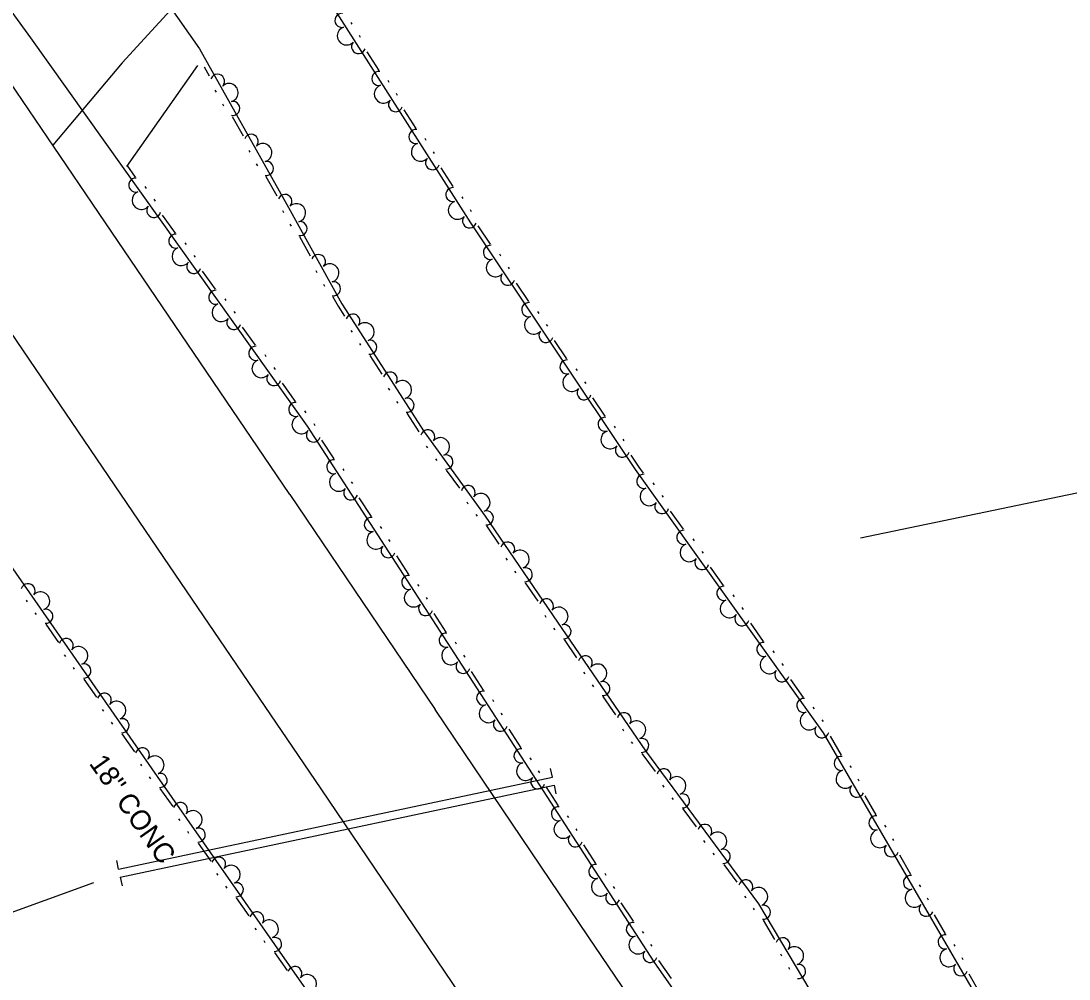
# Model space of a CAD drawing. Extents: x 2030130 to 2036320, y 723205 to 762423.
# Drawn here: x 2032932.6 to 2033126.1, y 761768 to 761944.8 of the extents above; entities that cross this region are included whole.
import ezdxf

# ---------------------------------------------------------------- set-up
doc = ezdxf.new("R2010")
doc.units = 0
for name, color, linetype in [('Draft_Station Labels Major', 7, 'Continuous'), ('Draft_Station Tics Major', 7, 'Continuous'), ('Draft_Station Tics Minor', 7, 'Continuous'), ('Old_Level_26', 7, 'Continuous'), ('Prop Alignment Horizontal', 7, 'Continuous')]:
    doc.layers.add(name, color=color, linetype=linetype)

msp = doc.modelspace()

# ---------------------------------------------------------------- linework, layer by layer
at = {"layer": 'Draft_Station Labels Major'}
for p, q in [((2032951.33, 761937.1), (2032938.5, 761921.91)), ((2032982.25, 761857.44), (2033009.06, 761817.74)), ((2032959.96, 761844.28), (2032987.95, 761803.12))]:
    msp.add_line(p, q, dxfattribs=at)
for points in [[(2032982.25, 761857.44), (2032953.98, 761899.13), (2032895.43, 761985.31), (2032867.48, 762026.64), (2032839.86, 762067.31), (2032810.94, 762109.31), (2032783.52, 762149.89), (2032755.69, 762190.54), (2032727.21, 762232.52), (2032699.29, 762273.24), (2032670.84, 762315.05), (2032643.99, 762354.39), (2032615.89, 762395.7), (2032597.19, 762422.99)], [(2032578.53, 762404.38), (2032622.03, 762340.46), (2032649.81, 762299.71), (2032677.92, 762258.76), (2032706.15, 762217.66), (2032734.05, 762176.43), (2032762.1, 762135.36), (2032790.25, 762094.19), (2032818.14, 762052.99), (2032846.2, 762011.84), (2032874.09, 761970.67), (2032902.04, 761929.59), (2032931.85, 761885.67), (2032959.96, 761844.28)], [(2032951.33, 761937.1), (2032972.48, 761960.26), (2032985.71, 761977.44)], [(2033317.86, 761363.04), (2033290.43, 761403.19), (2033260.47, 761446.88), (2033232.75, 761487.83), (2033204.6, 761528.87), (2033176.73, 761570.42), (2033148.96, 761611.47), (2033120.54, 761652.92), (2033093.45, 761693.44), (2033064.45, 761735.88), (2033037.38, 761775.77), (2033009.06, 761817.74)], [(2032987.95, 761803.12), (2033043.65, 761720.79), (2033056.64, 761702.34), (2033057.8, 761696.58), (2033076.72, 761668.89), (2033082.75, 761662.9), (2033099.45, 761638.44), (2033127.47, 761597.33), (2033155.33, 761556.18), (2033183.52, 761515.12), (2033211.27, 761473.78), (2033239.33, 761432.83), (2033268.78, 761389.51), (2033297.27, 761347.85)]]:
    msp.add_lwpolyline(points, dxfattribs=at)
at = {"layer": 'Draft_Station Tics Major'}
msp.add_line((2032952.18, 761917.95), (2032965.29, 761936.63), dxfattribs=at)
for points in [[(2033121.18, 761743.95), (2033080.74, 761813.47), (2033046.05, 761862.02), (2033015.65, 761907.58), (2032980.17, 761963.3), (2032941.81, 762027.2), (2032908.21, 762064.45), (2032877.87, 762105.34)], [(2033107.4, 761688.4), (2033049.51, 761771.21), (2032985.52, 761870.07), (2032934.46, 761941.71), (2032872.35, 762027.01), (2032832.35, 762090.98)], [(2032857.5, 762090.26), (2032871.14, 762073.87), (2032878.45, 762062.18), (2032888.1, 762049.28), (2032898.38, 762032.64), (2032910.79, 762015.75), (2032922.64, 761999.26), (2032936.88, 761980.71), (2032951.77, 761959.4), (2032965.55, 761939.68), (2032981.68, 761910.94), (2032991.86, 761892.63), (2033007.03, 761869.02), (2033018.32, 761853.44), (2033031.66, 761833.88), (2033047.89, 761810.12), (2033068.77, 761781.86), (2033086.33, 761752.31)], [(2032987.59, 761762.73), (2032957.8, 761805.4), (2032921.13, 761858.06), (2032890.88, 761904.34), (2032862.59, 761942.95), (2032834.05, 761983.65), (2032801.35, 762033.01), (2032781.96, 762059.34)], [(2032993.78, 761944.22), (2032993.56, 761944.57)], [(2032995.32, 761941.81), (2032995.1, 761942.15)], [(2032998.72, 761935.7), (2032996.52, 761939.16)], [(2032966.46, 761936.39), (2032967.39, 761934.73)], [(2033000.61, 761933.5), (2033000.39, 761933.85)], [(2032968.44, 761932.03), (2032968.64, 761931.67)], [(2033002.15, 761931.08), (2033001.93, 761931.43)], [(2032969.84, 761929.53), (2032970.04, 761929.17)], [(2032971.6, 761927.22), (2032973.61, 761923.65)], [(2033005.55, 761924.98), (2033003.35, 761928.44)], [(2033007.44, 761922.78), (2033007.21, 761923.12)], [(2032974.66, 761920.94), (2032974.86, 761920.59)], [(2033008.98, 761920.36), (2033008.76, 761920.7)], [(2032953.77, 761916.03), (2032952.21, 761918.22)], [(2032976.06, 761918.44), (2032976.26, 761918.08)], [(2033012.38, 761914.25), (2033010.17, 761917.71)], [(2032977.83, 761916.14), (2032979.83, 761912.56)], [(2032955.77, 761913.93), (2032955.53, 761914.26)], [(2032957.44, 761911.59), (2032957.2, 761911.92)], [(2033014.26, 761912.05), (2033014.04, 761912.4)], [(2032980.88, 761909.86), (2032981.08, 761909.5)], [(2033015.81, 761909.63), (2033015.58, 761909.98)], [(2032961.15, 761905.67), (2032958.77, 761909.01)], [(2032982.27, 761907.35), (2032982.47, 761906.99)], [(2033019.29, 761903.61), (2033017.01, 761907.02)], [(2032963.15, 761903.58), (2032962.91, 761903.91)], [(2032984.02, 761905.04), (2032986.01, 761901.46)], [(2033021.22, 761901.45), (2033021, 761901.79)], [(2032964.82, 761901.24), (2032964.58, 761901.57)], [(2032968.53, 761895.32), (2032966.15, 761898.66)], [(2032987.05, 761898.75), (2032987.25, 761898.39)], [(2033022.82, 761899.06), (2033022.59, 761899.4)], [(2032988.44, 761896.24), (2032988.64, 761895.88)], [(2033026.35, 761893.03), (2033024.07, 761896.44)], [(2032990.2, 761893.93), (2032991.15, 761892.2), (2032992.33, 761890.37)], [(2032970.53, 761893.22), (2032970.29, 761893.56)], [(2032972.2, 761890.88), (2032971.96, 761891.22)], [(2033028.28, 761890.87), (2033028.05, 761891.21)], [(2032975.91, 761884.97), (2032973.53, 761888.31)], [(2033029.87, 761888.48), (2033029.64, 761888.83)], [(2032993.54, 761887.73), (2032993.76, 761887.39)], [(2032995.09, 761885.32), (2032995.31, 761884.97)], [(2033033.4, 761882.46), (2033031.13, 761885.87)], [(2032977.91, 761882.87), (2032977.67, 761883.2)], [(2032996.99, 761883.12), (2032999.21, 761879.67)], [(2032979.58, 761880.53), (2032979.34, 761880.87)], [(2033035.34, 761880.3), (2033035.11, 761880.64)], [(2032983.29, 761874.62), (2032980.91, 761877.96)], [(2033000.42, 761877.04), (2033000.64, 761876.69)], [(2033036.93, 761877.91), (2033036.7, 761878.25)], [(2033001.97, 761874.62), (2033002.19, 761874.28)], [(2033040.46, 761871.88), (2033038.18, 761875.29)], [(2032985.29, 761872.52), (2032985.05, 761872.85)], [(2033003.87, 761872.43), (2033006.08, 761868.98)], [(2032986.96, 761870.11), (2032986.74, 761870.46)], [(2033042.39, 761869.72), (2033042.17, 761870.06)], [(2032990.41, 761864.04), (2032988.18, 761867.48)], [(2033043.98, 761867.33), (2033043.76, 761867.67)], [(2033007.44, 761866.36), (2033007.68, 761866.03)], [(2033009.12, 761864.04), (2033009.37, 761863.7)], [(2033047.54, 761861.35), (2033046.72, 761862.49), (2033045.24, 761864.72)], [(2032992.31, 761861.85), (2032992.09, 761862.2)], [(2033011.14, 761861.95), (2033013.55, 761858.63)], [(2032993.87, 761859.44), (2032993.64, 761859.79)], [(2033049.54, 761859.25), (2033049.3, 761859.59)], [(2033051.21, 761856.92), (2033050.97, 761857.25)], [(2032997.31, 761853.37), (2032995.08, 761856.81)], [(2033014.9, 761856.07), (2033015.14, 761855.74)], [(2033016.58, 761853.74), (2033016.82, 761853.41)], [(2033054.93, 761851.01), (2033052.54, 761854.34)], [(2032999.22, 761851.18), (2032998.99, 761851.52)], [(2033018.55, 761851.65), (2033020.86, 761848.26)], [(2033000.78, 761848.77), (2033000.55, 761849.11)], [(2033056.93, 761848.91), (2033056.69, 761849.24)], [(2033004.22, 761842.69), (2033001.99, 761846.14)], [(2033022.14, 761845.66), (2033022.37, 761845.32)], [(2033058.6, 761846.58), (2033058.36, 761846.91)], [(2033062.32, 761840.66), (2033059.93, 761844)], [(2033023.75, 761843.29), (2033023.99, 761842.95)], [(2033006.12, 761840.51), (2033005.9, 761840.85)], [(2033025.71, 761841.15), (2033028.02, 761837.76)], [(2032933.86, 761837.62), (2032933.63, 761837.95)], [(2033007.68, 761838.1), (2033007.46, 761838.44)], [(2033064.32, 761838.57), (2033064.08, 761838.9)], [(2033065.99, 761836.23), (2033065.75, 761836.56)], [(2032935.5, 761835.26), (2032935.27, 761835.6)], [(2033011.13, 761832.02), (2033008.9, 761835.46)], [(2033029.3, 761835.16), (2033029.53, 761834.82)], [(2032939.59, 761830.11), (2032937.25, 761833.48)], [(2033030.92, 761832.78), (2033031.15, 761832.45)], [(2033069.71, 761830.32), (2033067.32, 761833.66)], [(2033013.03, 761829.83), (2033012.81, 761830.18)], [(2033032.88, 761830.65), (2033035.19, 761827.26)], [(2033071.71, 761828.22), (2033071.47, 761828.56)], [(2032940.89, 761827.52), (2032940.66, 761827.86)], [(2033014.59, 761827.43), (2033014.37, 761827.77)], [(2033073.38, 761825.89), (2033073.14, 761826.22)], [(2032942.53, 761825.17), (2032942.3, 761825.5)], [(2033018.03, 761821.35), (2033015.81, 761824.79)], [(2033036.47, 761824.66), (2033036.7, 761824.32)], [(2032946.62, 761820.02), (2032944.28, 761823.38)], [(2033077.1, 761819.97), (2033074.71, 761823.31)], [(2033038.09, 761822.29), (2033038.32, 761821.95)], [(2033019.94, 761819.16), (2033019.72, 761819.51)], [(2033040.05, 761820.15), (2033042.36, 761816.76)], [(2032947.92, 761817.43), (2032947.69, 761817.76)], [(2033021.5, 761816.75), (2033021.28, 761817.1)], [(2033079.1, 761817.88), (2033078.86, 761818.21)], [(2032949.57, 761815.07), (2032949.33, 761815.41)], [(2033080.77, 761815.54), (2033080.53, 761815.87)], [(2032953.65, 761809.92), (2032951.31, 761813.29)], [(2033024.94, 761810.67), (2033022.71, 761814.12)], [(2033043.64, 761814.16), (2033043.87, 761813.82)], [(2033084.11, 761809.3), (2033082.05, 761812.84)], [(2033045.26, 761811.79), (2033045.49, 761811.45)], [(2033026.85, 761808.49), (2033026.62, 761808.83)], [(2033047.24, 761809.63), (2033049.67, 761806.33)], [(2032954.95, 761807.33), (2032954.72, 761807.66)], [(2033085.91, 761807.02), (2033085.71, 761807.38)], [(2032956.6, 761804.97), (2032956.36, 761805.31)], [(2033028.41, 761806.08), (2033028.18, 761806.42)], [(2032960.69, 761799.83), (2032958.34, 761803.19)], [(2033031.85, 761800), (2033029.62, 761803.45)], [(2033051.05, 761803.78), (2033051.29, 761803.45)], [(2033087.36, 761804.54), (2033087.15, 761804.9)], [(2033052.76, 761801.47), (2033053, 761801.14)], [(2033090.51, 761798.31), (2033088.44, 761801.85)], [(2033054.79, 761799.4), (2033057.23, 761796.1)], [(2032961.99, 761797.24), (2032961.76, 761797.57)], [(2033033.75, 761797.82), (2033033.53, 761798.16)], [(2033035.31, 761795.41), (2033035.09, 761795.75)], [(2033092.31, 761796.03), (2033092.1, 761796.39)], [(2032963.64, 761794.88), (2032963.4, 761795.22)], [(2033058.6, 761793.55), (2033058.85, 761793.22)], [(2033093.75, 761793.55), (2033093.54, 761793.91)], [(2032967.73, 761789.74), (2032965.38, 761793.1)], [(2033038.76, 761789.33), (2033036.53, 761792.77)], [(2033060.31, 761791.24), (2033060.55, 761790.91)], [(2033096.9, 761787.32), (2033094.84, 761790.86)], [(2033062.34, 761789.17), (2033064.78, 761785.87)], [(2032969.04, 761787.15), (2032968.8, 761787.49)], [(2033040.66, 761787.14), (2033040.44, 761787.49)], [(2032970.68, 761784.8), (2032970.45, 761785.13)], [(2033042.22, 761784.73), (2033042, 761785.08)], [(2033098.7, 761785.04), (2033098.49, 761785.4)], [(2032974.77, 761779.65), (2032972.42, 761783.01)], [(2033045.67, 761778.66), (2033043.44, 761782.1)], [(2033066.16, 761783.32), (2033066.4, 761782.99)], [(2033100.14, 761782.56), (2033099.94, 761782.92)], [(2033067.78, 761781.11), (2033067.99, 761780.75)], [(2033103.29, 761776.33), (2033101.23, 761779.88)], [(2033069.6, 761778.85), (2033071.7, 761775.32)], [(2032976.08, 761777.06), (2032975.84, 761777.4)], [(2033047.57, 761776.47), (2033047.35, 761776.81)], [(2032977.72, 761774.71), (2032977.49, 761775.04)], [(2033049.13, 761774.06), (2033048.91, 761774.4)], [(2033105.09, 761774.06), (2033104.89, 761774.41)], [(2032981.81, 761769.56), (2032979.47, 761772.92)], [(2033072.81, 761772.65), (2033073.02, 761772.29)], [(2033052.69, 761768.1), (2033050.34, 761771.46)], [(2033074.28, 761770.18), (2033074.49, 761769.83)], [(2033106.54, 761771.58), (2033106.33, 761771.93)], [(2033109.69, 761765.34), (2033107.62, 761768.89)]]:
    msp.add_lwpolyline(points, dxfattribs=at)
for centre, radius, start, end in [((2032991.86, 761944.95), 1.3, 83.2553, 284.0518), ((2032992.71, 761942.09), 1.69, 108.4506, 316.523), ((2032994.94, 761940.1), 1.3, 140.9217, 341.7183), ((2032968.91, 761933.7), 1.3, 317.7422, 158.5388), ((2032998.69, 761934.22), 1.3, 83.2553, 284.0518), ((2032971.03, 761931.6), 1.69, 285.271, 133.3435), ((2032999.54, 761931.36), 1.69, 108.4506, 316.523), ((2032971.72, 761928.7), 1.3, 260.0757, 100.8723), ((2033001.77, 761929.38), 1.3, 140.9217, 341.7183), ((2032975.13, 761922.62), 1.3, 317.7422, 158.5388), ((2033005.52, 761923.5), 1.3, 83.2553, 284.0518), ((2032977.25, 761920.52), 1.69, 285.271, 133.3435), ((2033006.37, 761920.64), 1.69, 108.4506, 316.523), ((2033008.6, 761918.66), 1.3, 140.9217, 341.7183), ((2032977.94, 761917.61), 1.3, 260.0757, 100.8723), ((2032953.82, 761914.55), 1.3, 86.2505, 287.047), ((2032954.82, 761911.73), 1.69, 111.4457, 319.5182), ((2033012.34, 761912.78), 1.3, 83.2553, 284.0518), ((2032981.35, 761911.53), 1.3, 317.7422, 158.5388), ((2033013.19, 761909.91), 1.69, 108.4506, 316.523), ((2032957.15, 761909.87), 1.3, 143.9169, 344.7135), ((2032983.47, 761909.42), 1.69, 285.0101, 133.0826), ((2032984.14, 761906.51), 1.3, 259.8148, 100.6114), ((2033015.43, 761907.93), 1.3, 140.9217, 341.7183), ((2032961.2, 761904.2), 1.3, 86.2505, 287.047), ((2032962.2, 761901.38), 1.69, 111.4457, 319.5182), ((2032987.53, 761900.42), 1.3, 317.4813, 158.2778), ((2033019.29, 761902.13), 1.3, 84.4785, 285.2751), ((2032964.53, 761899.52), 1.3, 143.9169, 344.7135), ((2032989.64, 761898.31), 1.69, 285.0101, 133.0826), ((2033020.2, 761899.29), 1.69, 109.6738, 317.7463), ((2033022.48, 761897.35), 1.3, 142.145, 342.9416), ((2032990.31, 761895.4), 1.3, 259.8148, 100.6114), ((2032968.58, 761893.84), 1.3, 86.2505, 287.047), ((2032969.58, 761891.03), 1.69, 111.4457, 319.5182), ((2033026.35, 761891.55), 1.3, 84.4785, 285.2751), ((2032993.91, 761889.43), 1.3, 321.1743, 161.9709), ((2033027.26, 761888.71), 1.69, 109.6738, 317.7463), ((2032971.91, 761889.17), 1.3, 143.9169, 344.7135), ((2032996.15, 761887.46), 1.69, 288.7031, 136.7756), ((2033029.53, 761886.78), 1.3, 142.145, 342.9416), ((2032975.96, 761883.49), 1.3, 86.2505, 287.047), ((2032997.01, 761884.6), 1.3, 263.5078, 104.3044), ((2032976.96, 761880.68), 1.69, 111.4457, 319.5182), ((2033033.4, 761880.98), 1.3, 84.4785, 285.2751), ((2032979.29, 761878.82), 1.3, 143.9169, 344.7135), ((2033000.79, 761878.74), 1.3, 321.1743, 161.9709), ((2033003.03, 761876.77), 1.69, 288.7031, 136.7756), ((2033034.31, 761878.13), 1.69, 109.6738, 317.7463), ((2033036.59, 761876.2), 1.3, 142.145, 342.9416), ((2033003.89, 761873.91), 1.3, 263.5078, 104.3044), ((2032983.34, 761873.14), 1.3, 86.2505, 287.047), ((2032984.34, 761870.33), 1.69, 111.4457, 319.5182), ((2033040.46, 761870.4), 1.3, 84.4785, 285.2751), ((2032986.6, 761868.41), 1.3, 141.3468, 342.1434), ((2033007.71, 761868.08), 1.3, 324.3576, 165.1542), ((2033041.37, 761867.56), 1.69, 109.6738, 317.7463), ((2033010.06, 761866.24), 1.69, 291.8864, 139.9589), ((2033043.64, 761865.63), 1.3, 142.145, 342.9416), ((2032990.38, 761862.56), 1.3, 83.6804, 284.4769), ((2033011.08, 761863.43), 1.3, 266.6912, 107.4877), ((2032991.26, 761859.71), 1.69, 108.8756, 316.9481), ((2033047.58, 761859.87), 1.3, 86.3128, 287.1094), ((2033015.17, 761857.79), 1.3, 324.3576, 165.1542), ((2032993.5, 761857.74), 1.3, 141.3468, 342.1434), ((2033017.52, 761855.94), 1.69, 291.8864, 139.9589), ((2033048.58, 761857.06), 1.69, 111.5081, 319.5806), ((2033050.92, 761855.2), 1.3, 143.9793, 344.7759), ((2033018.53, 761853.13), 1.3, 265.064, 105.8606), ((2032997.29, 761851.89), 1.3, 83.6804, 284.4769), ((2032998.16, 761849.03), 1.69, 108.8756, 316.9481), ((2033054.97, 761849.53), 1.3, 86.3128, 287.1094), ((2033000.41, 761847.07), 1.3, 141.3468, 342.1434), ((2033022.46, 761847.37), 1.3, 322.7305, 163.527), ((2033055.97, 761846.72), 1.69, 111.5081, 319.5806), ((2033024.76, 761845.46), 1.69, 290.2593, 138.3318), ((2033058.31, 761844.86), 1.3, 143.9793, 344.7759), ((2033025.7, 761842.63), 1.3, 265.064, 105.8606), ((2033004.2, 761841.22), 1.3, 83.6804, 284.4769), ((2032933.94, 761839.67), 1.3, 323.2844, 164.081), ((2033005.07, 761838.36), 1.69, 108.8756, 316.9481), ((2033062.36, 761839.19), 1.3, 86.3128, 287.1094), ((2032936.25, 761837.78), 1.69, 290.8132, 138.8857), ((2033029.62, 761836.87), 1.3, 322.7305, 163.527), ((2033063.37, 761836.37), 1.69, 111.5081, 319.5806), ((2032937.22, 761834.96), 1.3, 265.618, 106.4145), ((2033007.32, 761836.4), 1.3, 141.3468, 342.1434), ((2033031.92, 761834.96), 1.69, 290.2593, 138.3318), ((2033065.7, 761834.51), 1.3, 143.9793, 344.7759), ((2033032.86, 761832.12), 1.3, 265.1074, 105.904), ((2032940.97, 761829.57), 1.3, 323.2844, 164.081), ((2033011.11, 761830.54), 1.3, 83.6804, 284.4769), ((2033069.75, 761828.84), 1.3, 86.3128, 287.1094), ((2032943.28, 761827.68), 1.69, 290.8132, 138.8857), ((2033011.98, 761827.69), 1.69, 108.8756, 316.9481), ((2033014.23, 761825.72), 1.3, 141.3468, 342.1434), ((2033036.79, 761826.37), 1.3, 322.7739, 163.5704), ((2033070.76, 761826.03), 1.69, 111.5081, 319.5806), ((2032944.25, 761824.86), 1.3, 265.618, 106.4145), ((2033039.09, 761824.46), 1.69, 290.3027, 138.3751), ((2033073.09, 761824.17), 1.3, 143.9793, 344.7759), ((2033040.03, 761821.63), 1.3, 265.1074, 105.904), ((2032948, 761819.47), 1.3, 323.2844, 164.081), ((2033018.02, 761819.87), 1.3, 83.6804, 284.4769), ((2032950.31, 761817.59), 1.69, 290.8132, 138.8857), ((2033018.89, 761817.01), 1.69, 108.8756, 316.9481), ((2033077.15, 761818.5), 1.3, 86.3128, 287.1094), ((2033043.96, 761815.87), 1.3, 322.7739, 163.5704), ((2033078.15, 761815.68), 1.69, 111.5081, 319.5806), ((2032951.28, 761814.76), 1.3, 265.618, 106.4145), ((2033021.13, 761815.05), 1.3, 141.3468, 342.1434), ((2033046.26, 761813.96), 1.69, 290.3027, 138.3751), ((2033080.48, 761813.83), 1.3, 143.9793, 344.7759), ((2033047.2, 761811.13), 1.3, 265.1074, 105.904), ((2032955.03, 761809.38), 1.3, 323.2844, 164.081), ((2032957.34, 761807.49), 1.69, 290.8132, 138.8857), ((2033024.92, 761809.2), 1.3, 83.6804, 284.4769), ((2033084.02, 761807.82), 1.3, 80.9602, 281.7568), ((2033025.79, 761806.34), 1.69, 108.8756, 316.9481), ((2032958.31, 761804.67), 1.3, 265.6873, 106.4839), ((2033028.04, 761804.38), 1.3, 141.3468, 342.1434), ((2033051.31, 761805.5), 1.3, 324.8827, 165.6793), ((2033053.67, 761803.67), 1.69, 292.4115, 140.484), ((2033084.76, 761804.93), 1.69, 106.1555, 314.228), ((2033086.91, 761802.86), 1.3, 138.6267, 339.4232), ((2033054.72, 761800.88), 1.3, 267.2163, 108.0128), ((2032962.06, 761799.29), 1.3, 323.3538, 164.1504), ((2033031.83, 761798.52), 1.3, 83.6804, 284.4769), ((2032964.38, 761797.4), 1.69, 290.8826, 138.9551), ((2033032.7, 761795.67), 1.69, 108.8756, 316.9481), ((2033090.42, 761796.83), 1.3, 80.9602, 281.7568), ((2032965.35, 761794.58), 1.3, 265.6873, 106.4839), ((2033058.86, 761795.27), 1.3, 324.8827, 165.6793), ((2033091.15, 761793.94), 1.69, 106.1555, 314.228), ((2033034.95, 761793.7), 1.3, 141.3468, 342.1434), ((2033061.23, 761793.45), 1.69, 292.4115, 140.484), ((2033062.27, 761790.65), 1.3, 267.2163, 108.0128), ((2033093.3, 761791.87), 1.3, 138.6267, 339.4232), ((2032969.11, 761789.2), 1.3, 323.3538, 164.1504), ((2032971.42, 761787.31), 1.69, 290.8826, 138.9551), ((2033038.74, 761787.85), 1.3, 83.6804, 284.4769), ((2032972.39, 761784.49), 1.3, 265.6873, 106.4839), ((2033039.61, 761785), 1.69, 108.8756, 316.9481), ((2033066.41, 761785.04), 1.3, 324.8827, 165.6793), ((2033096.81, 761785.84), 1.3, 80.9602, 281.7568), ((2033041.86, 761783.03), 1.3, 141.3468, 342.1434), ((2033068.78, 761783.22), 1.69, 292.4115, 140.484), ((2033097.54, 761782.95), 1.69, 106.1555, 314.228), ((2033099.7, 761780.88), 1.3, 138.6267, 339.4232), ((2032976.15, 761779.11), 1.3, 323.3538, 164.1504), ((2033069.68, 761780.33), 1.3, 261.499, 102.2955), ((2032978.46, 761777.23), 1.69, 290.8826, 138.9551), ((2033045.65, 761777.18), 1.3, 83.6804, 284.4769), ((2033046.52, 761774.32), 1.69, 108.8756, 316.9481), ((2033103.2, 761774.86), 1.3, 80.9602, 281.7568), ((2032979.44, 761774.4), 1.3, 265.6873, 106.4839), ((2033073.24, 761774.33), 1.3, 319.1654, 159.962), ((2033075.41, 761772.28), 1.69, 286.6942, 134.7667), ((2033048.77, 761772.36), 1.3, 141.3468, 342.1434), ((2033103.94, 761771.96), 1.69, 106.1555, 314.228), ((2032983.19, 761769.02), 1.3, 323.3538, 164.1504), ((2033076.17, 761769.4), 1.3, 261.499, 102.2955), ((2033106.09, 761769.89), 1.3, 138.6267, 339.4232), ((2032985.51, 761767.14), 1.69, 290.8826, 138.9551)]:
    msp.add_arc(centre, radius, start, end, dxfattribs=at)
at = {"layer": 'Draft_Station Tics Minor'}
for p, q in [((2033030.72, 761805.24), (2033030.38, 761806.85)), ((2033031.03, 761803.8), (2033031.37, 761802.19)), ((2032950.64, 761788.28), (2032950.3, 761789.89)), ((2032950.95, 761786.84), (2032951.29, 761785.23))]:
    msp.add_line(p, q, dxfattribs=at)
for points in [[(2032950.64, 761788.28), (2033030.72, 761805.24)], [(2032950.95, 761786.84), (2033031.03, 761803.8)]]:
    msp.add_lwpolyline(points, dxfattribs=at)
at = {"layer": 'Prop Alignment Horizontal'}
msp.add_line((2033143.14, 761860.92), (2033087.6, 761849.37), dxfattribs=at)
msp.add_lwpolyline([(2032946.02, 761785.79), (2032927.96, 761779.26), (2032916.13, 761774.45), (2032907.84, 761770.26), (2032900.95, 761766.12)], dxfattribs=at)

# ---------------------------------------------------------------- texts
at = {"layer": 'Old_Level_26'}
msp.add_text('18" CONC', height=3.691, rotation=305.1848, dxfattribs=at).set_placement((2032945.08, 761807.81))

doc.saveas('drawing.dxf')
